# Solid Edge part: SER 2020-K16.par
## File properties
Author: LABUSIG
Template: iso metric part.par
Last saved by: LABUSIG
Revision: 1
Application: Solid Edge
Accuracy: 0.990
Username: LABUSIG
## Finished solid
Body 1: solid body, 38 faces, 108 edges, 72 vertices.
  Faces by surface: plane 23, cylinder 15
  Edges by curve: line 78, circle 30
Body 2: solid body, 63 faces, 183 edges, 122 vertices.
  Faces by surface: plane 42, cylinder 17, cone 4
  Edges by curve: line 126, circle 27, spline 18, curve on surface 12
Bounding box of the edges (mm): 20.052 x 22.610 x 124.037, from (-20.0524, 0, -124.0365) to (0, 22.6101, 0).
Cylindrical faces by radius (mm): R0.13 x6, R0.131 x6, R0.18 x2, R0.2 x3, R0.252 x3, R0.5 x1, R0.8 x1, R1.3 x1, R1.5875 x2, R1.75 x1, R2.5 x1, R2.7 x2, R3 x3
Conical faces (half-angle, radius in mm at the cone's reference point): 45 deg R0.38 x1, 88.5 deg R1.4207 x3
Planar faces by outward normal: +x 1, +y 2, +z 1, -x 1, -y 1, oblique 59
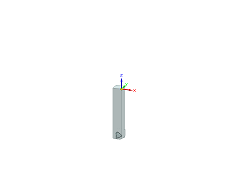
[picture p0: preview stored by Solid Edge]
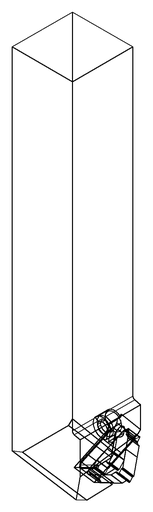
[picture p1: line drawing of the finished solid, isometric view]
